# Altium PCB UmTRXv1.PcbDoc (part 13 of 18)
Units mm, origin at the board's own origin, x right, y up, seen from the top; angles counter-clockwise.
Board outline 172 x 113 mm, 6 copper layers (Top Layer, GND, MidLayer1, Mid-Layer 2, InternalPlane2, Bottom Layer); 766 components, 613 nets, 3008 pads, 1360 vias.
Unrouted connection lines stored in the file: 2.
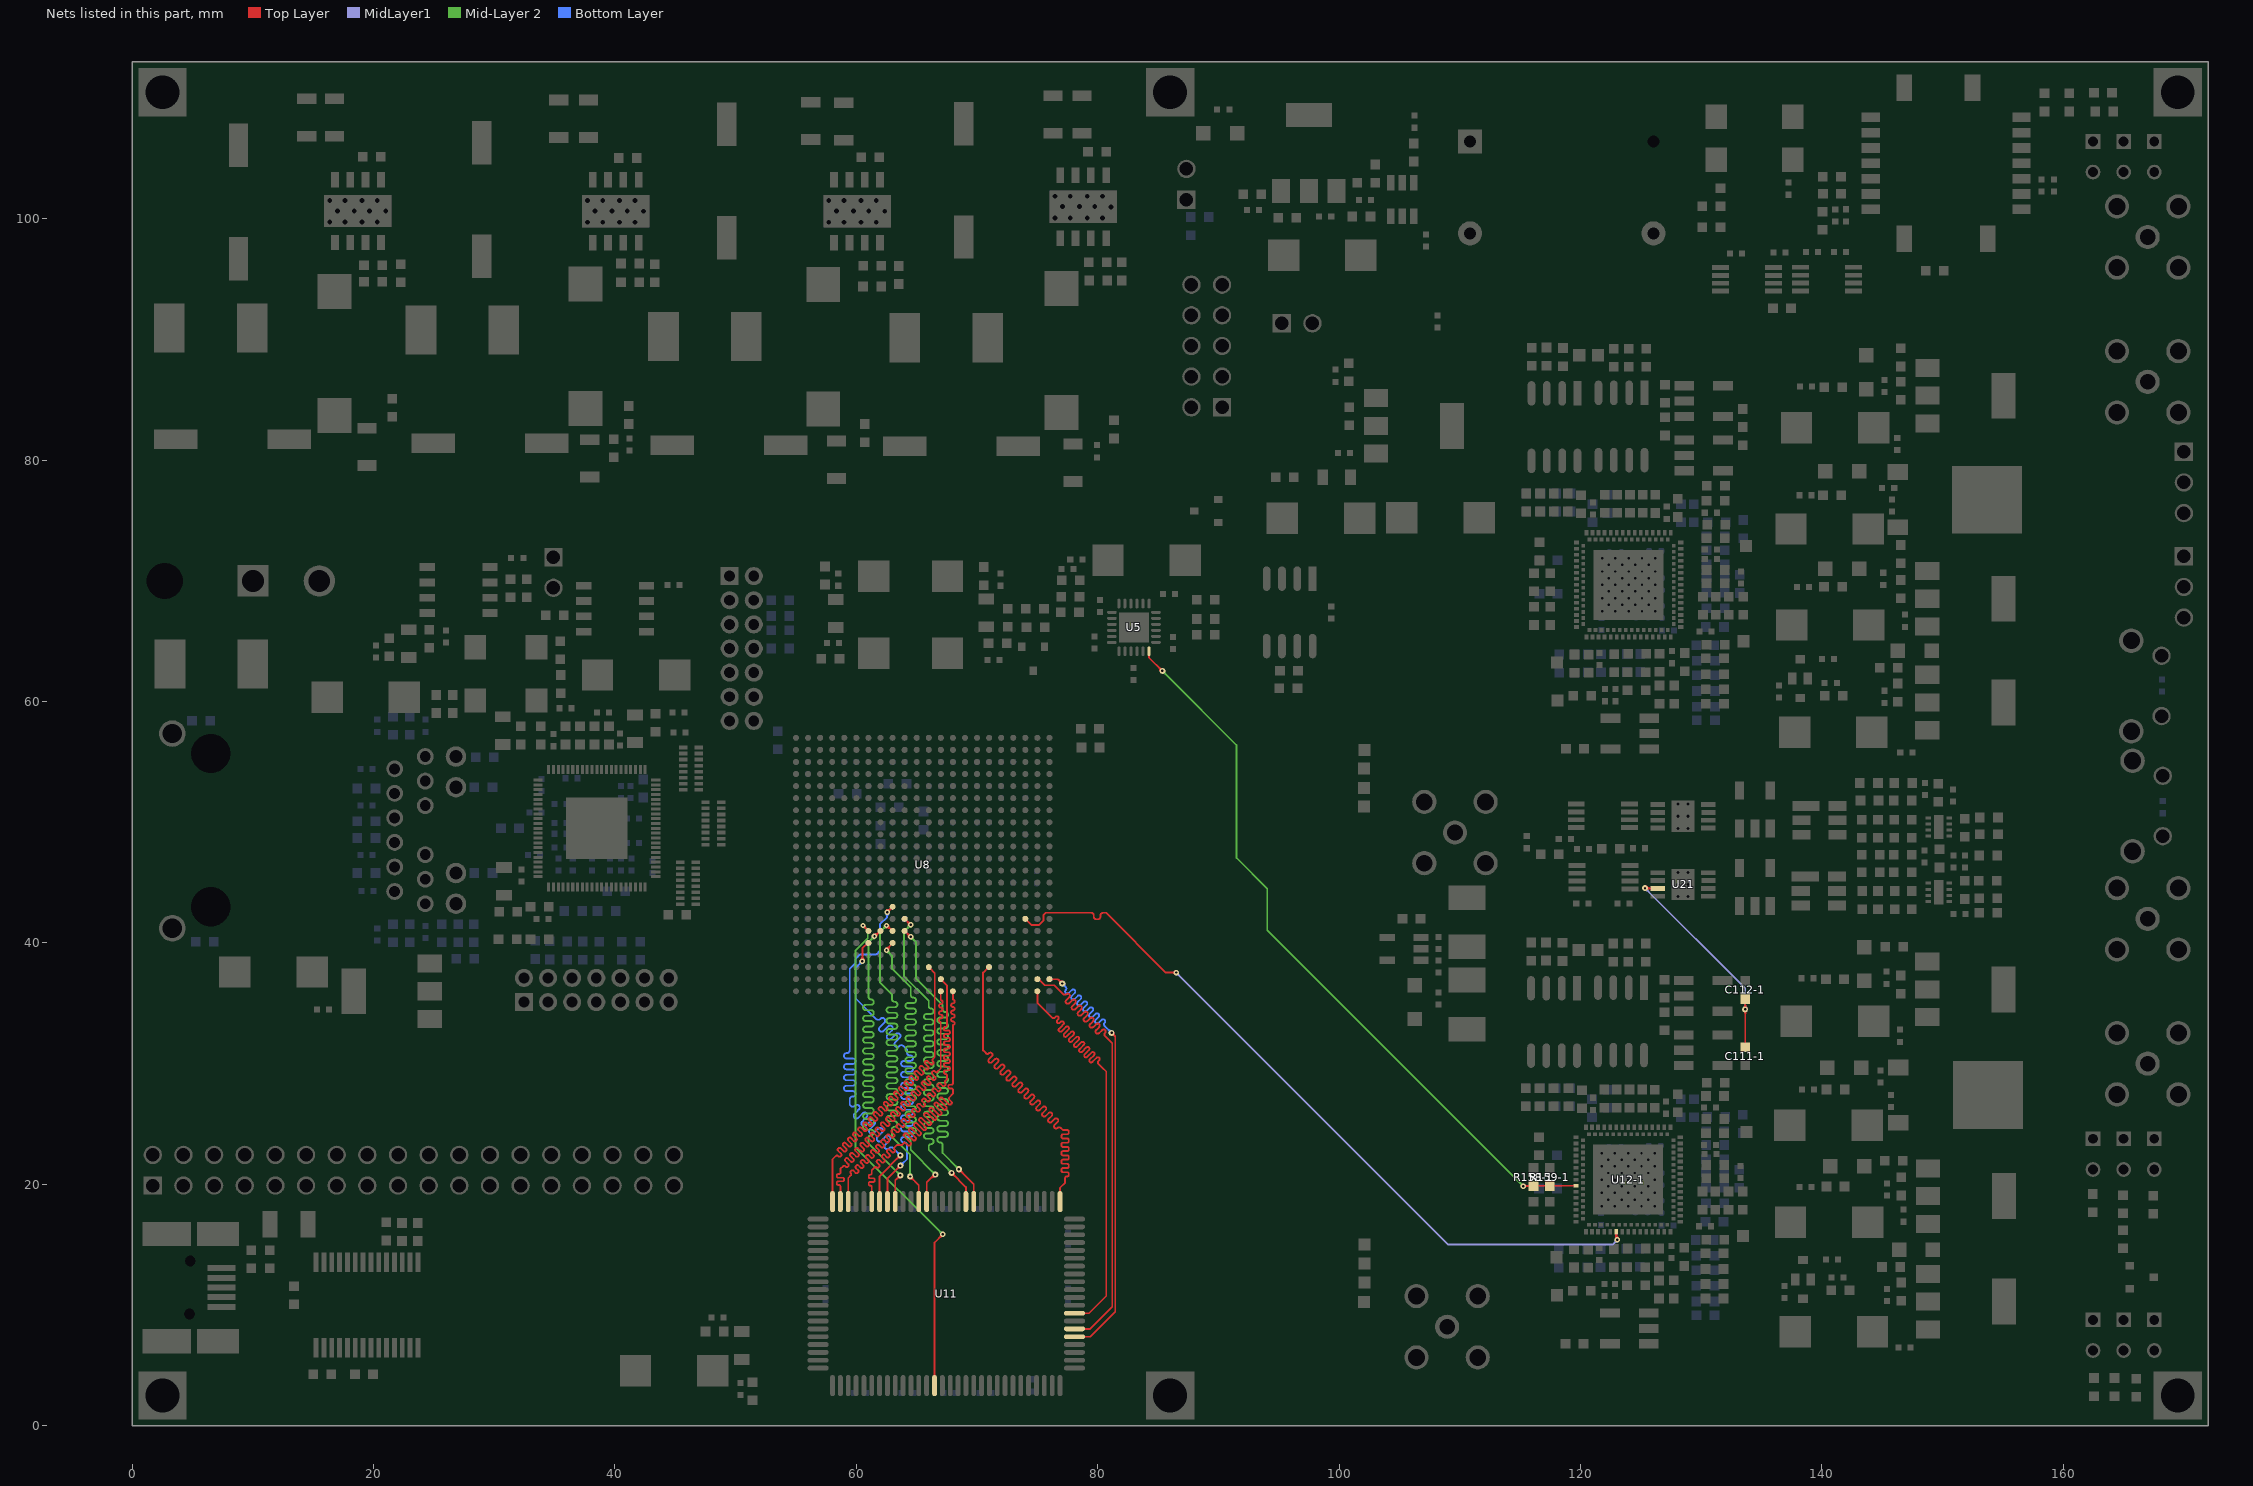
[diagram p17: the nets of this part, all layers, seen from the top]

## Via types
v1: diameter 0.45, hole 0.2, Top Layer to Bottom Layer, tented both sides, 554 vias
v2: diameter 0.5, hole 0.2, Top Layer to Bottom Layer, tented both sides, 468 vias
v3: diameter 0.7, hole 0.3, Top Layer to Bottom Layer, tented both sides, 206 vias
v4: diameter 0.4, hole 0.2, Top Layer to Bottom Layer, tented both sides, 82 vias
v5: diameter 0.8, hole 0.3, Top Layer to Bottom Layer, tented both sides, 16 vias
v6: diameter 0.6, hole 0.25, Top Layer to Bottom Layer, tented both sides, 16 vias
v7: diameter 0.5, hole 0.3, Top Layer to Bottom Layer, tented both sides, 8 vias
v8: diameter 0.7, hole 0.3, Top Layer to Bottom Layer, 4 vias
v9: diameter 0.6, hole 0.3, Top Layer to Bottom Layer, tented both sides, 4 vias
v10: diameter 0.5, hole 0.2, Top Layer to Bottom Layer, 2 vias

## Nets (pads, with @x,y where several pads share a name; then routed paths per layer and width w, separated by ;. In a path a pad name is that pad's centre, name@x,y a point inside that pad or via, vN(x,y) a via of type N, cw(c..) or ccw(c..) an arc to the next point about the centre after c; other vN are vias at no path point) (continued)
RAM_D24: U8.F13 U11.12 | length 44
  Top Layer w0.15: U8.F13@64,41 v1(64.5,40.5) ; v1@64.325,40.5 ccw(c63.903,40.5) 64.201,40.799 ccw(c64.5,41.097) v1@64.5,40.675 ; v2@68.5,21.075 cw(c68.5,20.653) 68.799,20.951 cw(c69.097,21.25) v2@68.675,21.25 ; v2(68.5,21.25) 69.725,20.025 U11.12@69.725,18.575
  Mid-Layer 2 w0.15: v1@64.5,40.325 cw(c64.5,39.903) 64.799,40.201 cw(c65.097,40.5) v1@64.675,40.5 ; v1(64.5,40.5) 64.95,40.05 64.95,37.05 67.15,34.85 67.15,34.5 ccw(c67.375,34.5) 67.375,34.275 cw(c67.375,34.05) 67.6,34.05 cw(c67.375,34.05) 67.375,33.825 66.931,33.825 ccw(c66.931,33.6) 66.706,33.6 ccw(c66.931,33.6) 66.931,33.375 67.369,33.375 cw(c67.369,33.15) 67.594,33.15 cw(c67.369,33.15) 67.369,32.925 66.931,32.925 ccw(c66.931,32.7) 66.706,32.7 ccw(c66.931,32.7) 66.931,32.475 67.369,32.475 cw(c67.369,32.25) 67.594,32.25 cw(c67.369,32.25) 67.369,32.025 66.931,32.025 ccw(c66.931,31.8) 66.706,31.8 ccw(c66.931,31.8) 66.931,31.575 67.369,31.575 cw(c67.369,31.35) 67.594,31.35 cw(c67.369,31.35) 67.369,31.125 66.931,31.125 ccw(c66.931,30.9) 66.706,30.9 ccw(c66.931,30.9) 66.931,30.675 67.369,30.675 cw(c67.369,30.45) 67.594,30.45 cw(c67.369,30.45) 67.369,30.225 66.931,30.225 ccw(c66.931,30) 66.706,30 ccw(c66.931,30) 66.931,29.775 67.369,29.775 cw(c67.369,29.55) 67.594,29.55 cw(c67.369,29.55) 67.369,29.325 66.931,29.325 ccw(c66.931,29.1) 66.706,29.1 ccw(c66.931,29.1) 66.931,28.875 67.369,28.875 cw(c67.369,28.65) 67.594,28.65 cw(c67.369,28.65) 67.369,28.425 66.931,28.425 ccw(c66.931,28.2) 66.706,28.2 ccw(c66.931,28.2) 66.931,27.975 67.369,27.975 cw(c67.369,27.75) 67.594,27.75 cw(c67.369,27.75) 67.369,27.525 66.931,27.525 ccw(c66.931,27.3) 66.706,27.3 ccw(c66.931,27.3) 66.931,27.075 67.369,27.075 cw(c67.369,26.85) 67.594,26.85 cw(c67.369,26.85) 67.369,26.625 66.931,26.625 ccw(c66.931,26.4) 66.706,26.4 ccw(c66.931,26.4) 66.931,26.175 67.369,26.175 cw(c67.369,25.95) 67.594,25.95 cw(c67.369,25.95) 67.369,25.725 66.931,25.725 ccw(c66.931,25.5) 66.706,25.5 ccw(c66.931,25.5) 66.931,25.275 67.369,25.275 cw(c67.369,25.05) 67.594,25.05 cw(c67.369,25.05) 67.369,24.825 66.931,24.825 ccw(c66.931,24.6) 66.706,24.6 ccw(c66.931,24.6) 66.931,24.375 67.369,24.375 cw(c67.369,24.15) 67.594,24.15 cw(c67.369,24.15) 67.369,23.925 66.931,23.925 ccw(c66.931,23.7) 66.706,23.7 ccw(c66.931,23.7) 66.925,23.475 ccw(c66.931,23.7) 66.931,23.475 ; v2@68.325,21.25 ccw(c67.903,21.25) 68.201,21.549 ccw(c68.5,21.847) v2@68.5,21.425 ; v2(68.5,21.25) 67.15,22.6 67.15,23.25 ccw(c66.925,23.25) 66.931,23.475 ; 66.931,23.475 ccw(c66.925,23.25) 66.925,23.475 66.931,23.475
RAM_D25: U8.G13 U11.13 | length 43.7
  Top Layer w0.15: U8.G13@64,42 v1(64.5,41.5) ; v1@64.325,41.5 ccw(c63.903,41.5) 64.201,41.799 ccw(c64.5,42.097) v1@64.5,41.675 ; v2@67.9,20.775 cw(c67.9,20.353) 68.199,20.651 cw(c68.497,20.95) v2@68.075,20.95 ; v2(67.9,20.95) 69.075,19.775 U11.13@69.075,18.575
  Mid-Layer 2 w0.15: v1@64.325,41.5 cw(c63.903,41.5) 64.201,41.201 cw(c64.5,40.903) v1@64.5,41.325 ; v1(64.5,41.5) 63.95,40.95 63.95,37.25 66,35.2 66,34.75 ccw(c66.175,34.75) 66.175,34.575 cw(c66.175,34.35) 66.4,34.35 cw(c66.175,34.35) 66.175,34.125 65.825,34.125 ccw(c65.825,33.9) 65.6,33.9 ccw(c65.825,33.9) 65.825,33.675 66.175,33.675 cw(c66.175,33.45) 66.4,33.45 cw(c66.175,33.45) 66.175,33.225 65.825,33.225 ccw(c65.825,33) 65.6,33 ccw(c65.825,33) 65.825,32.775 66.175,32.775 cw(c66.175,32.55) 66.4,32.55 cw(c66.175,32.55) 66.175,32.325 65.825,32.325 ccw(c65.825,32.1) 65.6,32.1 ccw(c65.825,32.1) 65.825,31.875 66.175,31.875 cw(c66.175,31.65) 66.4,31.65 cw(c66.175,31.65) 66.175,31.425 65.825,31.425 ccw(c65.825,31.2) 65.6,31.2 ccw(c65.825,31.2) 65.825,30.975 66.175,30.975 cw(c66.175,30.75) 66.4,30.75 cw(c66.175,30.75) 66.175,30.525 65.825,30.525 ccw(c65.825,30.3) 65.6,30.3 ccw(c65.825,30.3) 65.825,30.075 66.175,30.075 cw(c66.175,29.85) 66.4,29.85 cw(c66.175,29.85) 66.175,29.625 65.825,29.625 ccw(c65.825,29.4) 65.6,29.4 ccw(c65.825,29.4) 65.825,29.175 66.175,29.175 cw(c66.175,28.95) 66.4,28.95 cw(c66.175,28.95) 66.175,28.725 65.825,28.725 ccw(c65.825,28.5) 65.6,28.5 ccw(c65.825,28.5) 65.825,28.275 66.175,28.275 cw(c66.175,28.05) 66.4,28.05 cw(c66.175,28.05) 66.175,27.825 65.825,27.825 ccw(c65.825,27.6) 65.6,27.6 ccw(c65.825,27.6) 65.825,27.375 66.175,27.375 cw(c66.175,27.15) 66.4,27.15 cw(c66.175,27.15) 66.175,26.925 65.825,26.925 ccw(c65.825,26.7) 65.6,26.7 ccw(c65.825,26.7) 65.825,26.475 66.175,26.475 cw(c66.175,26.25) 66.4,26.25 cw(c66.175,26.25) 66.175,26.025 65.825,26.025 ccw(c65.825,25.8) 65.6,25.8 ccw(c65.825,25.8) 65.825,25.575 66.175,25.575 cw(c66.175,25.35) 66.4,25.35 cw(c66.175,25.35) 66.175,25.125 65.825,25.125 ccw(c65.825,24.9) 65.6,24.9 ccw(c65.825,24.9) 65.825,24.675 66.175,24.675 cw(c66.175,24.45) 66.4,24.45 cw(c66.175,24.45) 66.175,24.225 65.825,24.225 ccw(c65.825,24) 65.6,24 ccw(c65.825,24) 65.825,23.775 66.175,23.775 cw(c66.175,23.55) 66.4,23.55 cw(c66.175,23.55) 66.175,23.325 ccw(c66.175,23.15) 66,23.15 66,22.85 v2(67.9,20.95) ; v2@67.725,20.95 ccw(c67.303,20.95) 67.601,21.249 ccw(c67.9,21.547) v2@67.9,21.125
RAM_D26: U8.C6 U11.1 | length 41.2
  Top Layer w0.15: U8.C6@71,38 70.95,38 70.5,37.55 70.5,31.1 70.75,30.85 ccw(c70.862,30.962) 70.973,30.85 70.985,30.862 cw(c71.109,30.738) 71.233,30.862 cw(c71.109,30.738) 71.233,30.615 71.109,30.491 70.985,30.367 ccw(c71.109,30.243) 70.985,30.12 ccw(c71.109,30.243) 71.233,30.12 71.48,30.367 cw(c71.604,30.243) 71.728,30.367 cw(c71.604,30.243) 71.728,30.12 71.48,29.872 ccw(c71.604,29.748) 71.48,29.625 ccw(c71.604,29.748) 71.728,29.625 71.975,29.872 cw(c72.099,29.748) 72.223,29.872 cw(c72.099,29.748) 72.223,29.625 71.975,29.377 ccw(c72.099,29.254) 71.975,29.13 ccw(c72.099,29.254) 72.223,29.13 72.47,29.377 cw(c72.594,29.254) 72.718,29.377 cw(c72.594,29.254) 72.718,29.13 72.47,28.882 ccw(c72.594,28.759) 72.47,28.635 ccw(c72.594,28.759) 72.718,28.635 72.965,28.882 cw(c73.089,28.759) 73.213,28.882 cw(c73.089,28.759) 73.213,28.635 72.965,28.387 ccw(c73.089,28.264) 72.965,28.14 ccw(c73.089,28.264) 73.213,28.14 73.46,28.387 cw(c73.584,28.264) 73.708,28.387 cw(c73.584,28.264) 73.708,28.14 73.46,27.892 ccw(c73.584,27.769) 73.46,27.645 ccw(c73.584,27.769) 73.708,27.645 73.955,27.892 cw(c74.079,27.769) 74.203,27.892 cw(c74.079,27.769) 74.203,27.645 73.955,27.397 ccw(c74.079,27.274) 73.955,27.15 ccw(c74.079,27.274) 74.203,27.15 74.45,27.397 cw(c74.574,27.274) 74.698,27.397 cw(c74.574,27.274) 74.698,27.15 74.574,27.026 74.45,26.902 ccw(c74.574,26.779) 74.45,26.655 ccw(c74.574,26.779) 74.698,26.655 74.945,26.902 cw(c75.069,26.779) 75.193,26.902 cw(c75.069,26.779) 75.193,26.655 74.945,26.407 ccw(c75.069,26.284) 74.945,26.16 ccw(c75.069,26.284) 75.193,26.16 75.44,26.407 cw(c75.564,26.284) 75.688,26.407 cw(c75.564,26.284) 75.688,26.16 75.44,25.912 ccw(c75.564,25.789) 75.44,25.665 ccw(c75.564,25.789) 75.688,25.665 75.935,25.912 cw(c76.059,25.789) 76.183,25.912 cw(c76.059,25.789) 76.183,25.665 75.935,25.417 ccw(c76.059,25.294) 75.935,25.17 ccw(c76.059,25.294) 76.183,25.17 76.43,25.417 cw(c76.554,25.294) 76.678,25.417 cw(c76.554,25.294) 76.678,25.17 76.43,24.922 ccw(c76.554,24.799) 76.43,24.675 ccw(c76.554,24.799) 76.678,24.675 cw(c76.801,24.551) 76.925,24.675 77.1,24.5 77.477,24.5 cw(c77.477,24.377) 77.6,24.377 77.6,24.272 cw(c77.477,24.272) 77.477,24.15 77.122,24.15 ccw(c77.122,24.027) 77,24.027 77,23.922 ccw(c77.122,23.922) 77.122,23.8 77.477,23.8 cw(c77.477,23.677) 77.6,23.677 77.6,23.572 cw(c77.477,23.572) 77.477,23.45 77.122,23.45 ccw(c77.122,23.327) 77,23.327 77,23.222 ccw(c77.122,23.222) 77.122,23.1 77.477,23.1 cw(c77.477,22.977) 77.6,22.977 77.6,22.872 cw(c77.477,22.872) 77.477,22.75 77.122,22.75 ccw(c77.122,22.627) 77,22.627 77,22.522 ccw(c77.122,22.522) 77.122,22.4 77.477,22.4 cw(c77.477,22.277) 77.6,22.277 77.6,22.172 cw(c77.477,22.172) 77.477,22.05 77.122,22.05 ccw(c77.122,21.927) 77,21.927 77,21.822 ccw(c77.122,21.822) 77.122,21.7 77.477,21.7 cw(c77.477,21.577) 77.6,21.577 77.6,21.472 cw(c77.477,21.472) 77.477,21.35 77.122,21.35 ccw(c77.122,21.227) 77,21.227 77,21.122 ccw(c77.122,21.122) 77.122,21 77.477,21 cw(c77.477,20.877) 77.6,20.877 77.6,20.772 cw(c77.477,20.772) 77.477,20.65 77.422,20.65 ccw(c77.422,20.528) 77.3,20.528 77.3,20.125 76.875,19.7 U11.1@76.875,18.575
RAM_D27: U8.E14 U11.18 | length 44
  Top Layer w0.15: v1(62.5,39.4) 62.5,39.5 U8.E14@63,40 ; v1@62.5,39.575 ccw(c62.5,39.756) 62.628,39.628 ; v1@62.675,39.4 cw(c63.339,39.4) U8.E14@62.869,39.869 ; U11.18@65.825,18.575 65.825,20.175 66.45,20.8 v2(66.55,20.8) ; 66.081,20.431 cw(c66.55,19.961) v2@66.55,20.625 ; 66.322,20.672 ccw(c66.194,20.8) v2@66.375,20.8
  Mid-Layer 2 w0.15: v1@62.5,39.225 cw(c62.5,38.803) 62.799,39.101 cw(c63.097,39.4) v1@62.675,39.4 ; v1(62.5,39.4) 62.95,38.95 62.95,37.896 64.5,36.346 64.5,35.7 ccw(c64.725,35.7) 64.725,35.475 cw(c64.725,35.25) 64.95,35.25 cw(c64.725,35.25) 64.725,35.025 64.287,35.025 ccw(c64.287,34.8) 64.062,34.8 ccw(c64.287,34.8) 64.287,34.575 64.713,34.575 cw(c64.713,34.35) 64.938,34.35 cw(c64.713,34.35) 64.713,34.125 64.287,34.125 ccw(c64.287,33.9) 64.062,33.9 ccw(c64.287,33.9) 64.287,33.675 64.713,33.675 cw(c64.713,33.45) 64.938,33.45 cw(c64.713,33.45) 64.713,33.225 64.287,33.225 ccw(c64.287,33) 64.062,33 ccw(c64.287,33) 64.287,32.775 64.713,32.775 cw(c64.713,32.55) 64.938,32.55 cw(c64.713,32.55) 64.713,32.325 64.287,32.325 ccw(c64.287,32.1) 64.062,32.1 ccw(c64.287,32.1) 64.287,31.875 64.713,31.875 cw(c64.713,31.65) 64.938,31.65 cw(c64.713,31.65) 64.713,31.425 64.287,31.425 ccw(c64.287,31.2) 64.062,31.2 ccw(c64.287,31.2) 64.287,30.975 64.713,30.975 cw(c64.713,30.75) 64.938,30.75 cw(c64.713,30.75) 64.713,30.525 64.287,30.525 ccw(c64.287,30.3) 64.062,30.3 ccw(c64.287,30.3) 64.287,30.075 64.713,30.075 cw(c64.713,29.85) 64.938,29.85 cw(c64.713,29.85) 64.713,29.625 64.287,29.625 ccw(c64.287,29.4) 64.062,29.4 ccw(c64.287,29.4) 64.287,29.175 64.713,29.175 cw(c64.713,28.95) 64.938,28.95 cw(c64.713,28.95) 64.713,28.725 64.287,28.725 ccw(c64.287,28.5) 64.062,28.5 ccw(c64.287,28.5) 64.287,28.275 64.713,28.275 cw(c64.713,28.05) 64.938,28.05 cw(c64.713,28.05) 64.713,27.825 64.286,27.825 ccw(c64.286,27.6) 64.062,27.6 ccw(c64.286,27.6) 64.286,27.375 64.713,27.375 cw(c64.713,27.15) 64.938,27.15 cw(c64.713,27.15) 64.713,26.925 64.286,26.925 ccw(c64.286,26.7) 64.062,26.7 ccw(c64.286,26.7) 64.286,26.475 64.713,26.475 cw(c64.713,26.25) 64.938,26.25 cw(c64.713,26.25) 64.713,26.025 64.286,26.025 ccw(c64.286,25.8) 64.062,25.8 ccw(c64.286,25.8) 64.286,25.575 64.713,25.575 cw(c64.713,25.35) 64.938,25.35 cw(c64.713,25.35) 64.713,25.125 64.286,25.125 ccw(c64.286,24.9) 64.062,24.9 ccw(c64.286,24.9) 64.286,24.675 64.713,24.675 cw(c64.713,24.45) 64.938,24.45 cw(c64.713,24.45) 64.713,24.225 64.286,24.225 ccw(c64.286,24) 64.062,24 ccw(c64.286,24) 64.286,23.775 64.325,23.775 cw(c64.325,23.6) 64.5,23.6 64.5,22.85 v2(66.55,20.8) ; v2@66.375,20.8 ccw(c65.953,20.8) 66.251,21.099 ccw(c66.55,21.397) v2@66.55,20.975
RAM_D28: U8.F14 U11.19 | length 43.9
  Top Layer w0.15: v1@62.5,41.275 cw(c62.5,40.732) U8.F14@62.884,41.116 ; v1(62.5,41.45) 62.55,41.45 U8.F14@63,41 ; v1@62.675,41.45 ccw(c62.977,41.45) 62.763,41.237 ; v2@64.45,20.475 cw(c64.45,20.053) 64.749,20.351 cw(c65.047,20.65) v2@64.625,20.65 ; v2(64.45,20.65) 65.175,19.925 U11.19@65.175,18.575
  Mid-Layer 2 w0.15: v1@62.325,41.45 cw(c61.903,41.45) 62.201,41.151 cw(c62.5,40.853) v1@62.5,41.275 ; v1@62.6,41.45 v1(62.5,41.45) 61.95,40.9 61.95,36.75 62.95,35.75 62.95,35.35 ccw(c63.175,35.35) 63.175,35.125 cw(c63.175,34.9) 63.4,34.9 cw(c63.175,34.9) 63.175,34.675 62.725,34.675 ccw(c62.725,34.45) 62.5,34.45 ccw(c62.725,34.45) 62.725,34.225 63.175,34.225 cw(c63.175,34) 63.4,34 cw(c63.175,34) 63.175,33.775 62.725,33.775 ccw(c62.725,33.55) 62.5,33.55 ccw(c62.725,33.55) 62.725,33.325 63.175,33.325 cw(c63.175,33.1) 63.4,33.1 cw(c63.175,33.1) 63.175,32.875 62.725,32.875 ccw(c62.725,32.65) 62.5,32.65 ccw(c62.725,32.65) 62.725,32.425 63.175,32.425 cw(c63.175,32.2) 63.4,32.2 cw(c63.175,32.2) 63.175,31.975 62.725,31.975 ccw(c62.725,31.75) 62.5,31.75 ccw(c62.725,31.75) 62.725,31.525 63.175,31.525 cw(c63.175,31.3) 63.4,31.3 cw(c63.175,31.3) 63.175,31.075 62.725,31.075 ccw(c62.725,30.85) 62.5,30.85 ccw(c62.725,30.85) 62.725,30.625 63.175,30.625 cw(c63.175,30.4) 63.4,30.4 cw(c63.175,30.4) 63.175,30.175 62.725,30.175 ccw(c62.725,29.95) 62.5,29.95 ccw(c62.725,29.95) 62.725,29.725 63.175,29.725 cw(c63.175,29.5) 63.4,29.5 cw(c63.175,29.5) 63.175,29.275 62.725,29.275 ccw(c62.725,29.05) 62.5,29.05 ccw(c62.725,29.05) 62.725,28.825 63.175,28.825 cw(c63.175,28.6) 63.4,28.6 cw(c63.175,28.6) 63.175,28.375 62.725,28.375 ccw(c62.725,28.15) 62.5,28.15 ccw(c62.725,28.15) 62.725,27.925 63.175,27.925 cw(c63.175,27.7) 63.4,27.7 cw(c63.175,27.7) 63.175,27.475 62.725,27.475 ccw(c62.725,27.25) 62.5,27.25 ccw(c62.725,27.25) 62.725,27.025 63.175,27.025 cw(c63.175,26.8) 63.4,26.8 cw(c63.175,26.8) 63.175,26.575 62.725,26.575 ccw(c62.725,26.35) 62.5,26.35 ccw(c62.725,26.35) 62.725,26.125 63.175,26.125 cw(c63.175,25.9) 63.4,25.9 cw(c63.175,25.9) 63.175,25.675 62.725,25.675 ccw(c62.725,25.45) 62.5,25.45 ccw(c62.725,25.45) 62.725,25.225 63.175,25.225 cw(c63.175,25) 63.4,25 cw(c63.175,25) 63.175,24.775 ccw(c63.175,24.55) 62.95,24.55 62.95,23.95 64.45,22.45 v2(64.45,20.65) ; v2@64.326,20.774 ccw(c64.028,21.072) 64.45,21.072 ccw(c64.872,21.072) v2@64.574,20.774
RAM_D29: U8.F15 U11.22 | length 44
  Top Layer w0.15: v1(61.5,40.55) 61.55,40.55 U8.F15@62,41 ; v1@61.5,40.725 ccw(c61.5,41.268) U8.F15@61.884,40.884 ; v1@61.675,40.55 cw(c61.977,40.55) 61.763,40.763 ; U11.22@63.225,18.575 63.225,20.325 v2(63.65,20.75) ; v2@63.475,20.75 cw(c63.053,20.75) 63.351,20.451 cw(c63.65,20.153) v2@63.65,20.575
  Mid-Layer 2 w0.15: v1@61.325,40.55 cw(c60.903,40.55) 61.201,40.251 cw(c61.5,39.953) v1@61.5,40.375 ; v1(61.5,40.55) 61,40.05 61,35.55 ccw(c61.225,35.55) 61.219,35.325 ; v2@63.475,20.75 ccw(c63.053,20.75) 63.351,21.049 ccw(c63.65,21.347) v2@63.65,20.925 ; v2(63.65,20.75) 61,23.4 61,23.85 cw(c61.225,23.85) 61.225,24.075 ccw(c61.225,24.3) 61.45,24.3 ccw(c61.225,24.3) 61.225,24.525 60.782,24.525 cw(c60.782,24.75) 60.557,24.75 cw(c60.782,24.75) 60.782,24.975 61.218,24.975 ccw(c61.218,25.2) 61.443,25.2 ccw(c61.218,25.2) 61.218,25.425 60.782,25.425 cw(c60.782,25.65) 60.557,25.65 cw(c60.782,25.65) 60.782,25.875 61.218,25.875 ccw(c61.218,26.1) 61.443,26.1 ccw(c61.218,26.1) 61.218,26.325 60.782,26.325 cw(c60.782,26.55) 60.557,26.55 cw(c60.782,26.55) 60.782,26.775 61.218,26.775 ccw(c61.218,27) 61.443,27 ccw(c61.218,27) 61.218,27.225 60.782,27.225 cw(c60.782,27.45) 60.557,27.45 cw(c60.782,27.45) 60.782,27.675 61.218,27.675 ccw(c61.218,27.9) 61.443,27.9 ccw(c61.218,27.9) 61.218,28.125 60.782,28.125 cw(c60.782,28.35) 60.557,28.35 cw(c60.782,28.35) 60.782,28.575 61.218,28.575 ccw(c61.218,28.8) 61.443,28.8 ccw(c61.218,28.8) 61.218,29.025 60.782,29.025 cw(c60.782,29.25) 60.557,29.25 cw(c60.782,29.25) 60.782,29.475 61.218,29.475 ccw(c61.218,29.7) 61.443,29.7 ccw(c61.218,29.7) 61.218,29.925 60.782,29.925 cw(c60.782,30.15) 60.557,30.15 cw(c60.782,30.15) 60.782,30.375 61.218,30.375 ccw(c61.218,30.6) 61.443,30.6 ccw(c61.218,30.6) 61.218,30.825 60.782,30.825 cw(c60.782,31.05) 60.557,31.05 cw(c60.782,31.05) 60.782,31.275 61.218,31.275 ccw(c61.218,31.5) 61.443,31.5 ccw(c61.218,31.5) 61.218,31.725 60.782,31.725 cw(c60.782,31.95) 60.557,31.95 cw(c60.782,31.95) 60.782,32.175 61.218,32.175 ccw(c61.218,32.4) 61.443,32.4 ccw(c61.218,32.4) 61.218,32.625 60.782,32.625 cw(c60.782,32.85) 60.557,32.85 cw(c60.782,32.85) 60.782,33.075 61.218,33.075 ccw(c61.218,33.3) 61.443,33.3 ccw(c61.218,33.3) 61.218,33.525 60.782,33.525 cw(c60.782,33.75) 60.557,33.75 cw(c60.782,33.75) 60.782,33.975 61.218,33.975 ccw(c61.218,34.2) 61.443,34.2 ccw(c61.218,34.2) 61.218,34.425 60.782,34.425 cw(c60.782,34.65) 60.557,34.65 cw(c60.782,34.65) 60.782,34.875 61.218,34.875 ccw(c61.218,35.1) 61.443,35.1 ccw(c61.218,35.1) 61.224,35.325 ; 61.219,35.325 ccw(c61.225,35.55) 61.224,35.325 ; 61.219,35.325 cw(c61.218,35.1) 61.224,35.325 ; 61.219,35.325 61.224,35.325
RAM_D30: U8.E16 U11.23 | length 44
  Top Layer w0.15: v1@60.376,38.624 ccw(c60.078,38.922) 60.5,38.922 ccw(c60.922,38.922) v1@60.624,38.624 ; v1(60.5,38.5) 60.5,39.55 U8.E16@60.975,40.025 ; U11.23@62.575,18.575 62.575,20.475 v2(63.65,21.55) ; v2@63.475,21.55 cw(c63.053,21.55) 63.351,21.251 cw(c63.65,20.953) v2@63.65,21.375
  Bottom Layer w0.15: v1@60.325,38.5 cw(c59.903,38.5) 60.201,38.201 cw(c60.5,37.903) v1@60.5,38.325 ; v1(60.5,38.5) 59.95,37.95 59.95,35.4 61.654,33.696 ccw(c61.814,33.855) 61.973,33.696 62.002,33.725 cw(c62.161,33.566) 62.32,33.725 cw(c62.161,33.566) 62.32,33.407 62.132,33.218 61.943,33.03 ccw(c62.102,32.871) 61.943,32.712 ccw(c62.102,32.871) 62.261,32.712 62.45,32.9 62.638,33.089 cw(c62.797,32.929) 62.957,33.089 cw(c62.797,32.929) 62.957,32.77 62.768,32.582 62.58,32.393 ccw(c62.739,32.234) 62.58,32.075 ccw(c62.739,32.234) 62.898,32.075 63.086,32.264 63.275,32.452 cw(c63.434,32.293) 63.593,32.452 cw(c63.434,32.293) 63.593,32.134 63.405,31.945 63.216,31.757 ccw(c63.375,31.598) 63.216,31.439 ccw(c63.375,31.598) 63.534,31.439 63.564,31.468 cw(c63.723,31.309) 63.882,31.468 64.2,31.15 64.2,30.9 ccw(c64.425,30.9) 64.425,30.675 64.467,30.675 cw(c64.467,30.45) 64.692,30.45 cw(c64.467,30.45) 64.467,30.225 63.933,30.225 ccw(c63.933,30) 63.708,30 ccw(c63.933,30) 63.933,29.775 64.467,29.775 cw(c64.467,29.55) 64.692,29.55 cw(c64.467,29.55) 64.467,29.325 63.933,29.325 ccw(c63.933,29.1) 63.708,29.1 ccw(c63.933,29.1) 63.933,28.875 64.467,28.875 cw(c64.467,28.65) 64.692,28.65 cw(c64.467,28.65) 64.467,28.425 63.933,28.425 ccw(c63.933,28.2) 63.708,28.2 ccw(c63.933,28.2) 63.933,27.975 64.467,27.975 cw(c64.467,27.75) 64.692,27.75 cw(c64.467,27.75) 64.467,27.525 63.933,27.525 ccw(c63.933,27.3) 63.708,27.3 ccw(c63.933,27.3) 63.933,27.075 64.467,27.075 cw(c64.467,26.85) 64.692,26.85 cw(c64.467,26.85) 64.467,26.625 63.933,26.625 ccw(c63.933,26.4) 63.708,26.4 ccw(c63.933,26.4) 63.933,26.175 64.467,26.175 cw(c64.467,25.95) 64.692,25.95 cw(c64.467,25.95) 64.467,25.725 63.933,25.725 ccw(c63.933,25.5) 63.708,25.5 ccw(c63.933,25.5) 63.933,25.275 64.467,25.275 cw(c64.467,25.05) 64.692,25.05 cw(c64.467,25.05) 64.467,24.825 63.933,24.825 ccw(c63.933,24.6) 63.708,24.6 ccw(c63.933,24.6) 63.933,24.375 64.467,24.375 cw(c64.467,24.15) 64.692,24.15 cw(c64.467,24.15) 64.467,23.925 63.933,23.925 ccw(c63.933,23.7) 63.708,23.7 ccw(c63.933,23.7) 63.933,23.475 63.975,23.475 cw(c63.975,23.25) 64.2,23.25 64.2,22.1 v2(63.65,21.55) ; v2@63.65,21.725 ccw(c63.65,22.147) 63.949,21.849 ccw(c64.247,21.55) v2@63.825,21.55
RAM_D31: U8.H14 U11.24 | length 45.4
  Top Layer w0.15: U11.24@61.925,18.575 61.925,20.675 v2(63.65,22.4) ; v1@62.55,42.65 v1(62.55,42.55) U8.H14@63,43 ; v1@62.55,42.725 ccw(c62.55,43.147) 62.849,42.849 ccw(c63.147,42.55) v1@62.725,42.55 ; v2@63.475,22.4 cw(c63.053,22.4) 63.351,22.101 cw(c63.65,21.803) v2@63.65,22.225
  Bottom Layer w0.15: 61.675,39.075 61.65,39.05 60.325,39.05 59.925,38.65 59.925,38.324 59.45,37.849 59.45,31.1 cw(c59.225,31.1) 59.225,30.875 59.191,30.875 ccw(c59.191,30.65) 58.966,30.65 ccw(c59.191,30.65) 59.191,30.425 59.709,30.425 cw(c59.709,30.2) 59.934,30.2 cw(c59.709,30.2) 59.709,29.975 59.191,29.975 ccw(c59.191,29.75) 58.966,29.75 ccw(c59.191,29.75) 59.191,29.525 59.709,29.525 cw(c59.709,29.3) 59.934,29.3 cw(c59.709,29.3) 59.709,29.075 59.191,29.075 ccw(c59.191,28.85) 58.966,28.85 ccw(c59.191,28.85) 59.191,28.625 59.709,28.625 cw(c59.709,28.4) 59.934,28.4 cw(c59.709,28.4) 59.709,28.175 59.191,28.175 ccw(c59.191,27.95) 58.966,27.95 ccw(c59.191,27.95) 59.191,27.725 59.709,27.725 cw(c59.709,27.5) 59.934,27.5 cw(c59.709,27.5) 59.709,27.275 59.675,27.275 ccw(c59.675,27.05) 59.45,27.05 59.45,26.6 59.55,26.5 ccw(c59.709,26.659) 59.868,26.5 59.892,26.524 cw(c60.051,26.365) 60.21,26.524 cw(c60.051,26.365) 60.21,26.206 60.027,26.023 59.844,25.84 ccw(c60.003,25.681) 59.844,25.522 ccw(c60.003,25.681) 60.162,25.522 60.345,25.705 60.528,25.888 cw(c60.687,25.729) 60.847,25.888 cw(c60.687,25.729) 60.847,25.57 60.664,25.386 60.48,25.203 ccw(c60.64,25.044) 60.48,24.885 ccw(c60.64,25.044) 60.799,24.885 60.982,25.068 61.165,25.251 cw(c61.324,25.092) 61.483,25.251 cw(c61.324,25.092) 61.483,24.933 61.3,24.75 61.117,24.567 ccw(c61.276,24.408) 61.117,24.249 ccw(c61.276,24.408) 61.435,24.249 61.618,24.432 61.801,24.615 cw(c61.96,24.456) 62.119,24.615 cw(c61.96,24.456) 62.119,24.297 61.936,24.114 61.753,23.931 ccw(c61.912,23.772) 61.753,23.612 ccw(c61.912,23.772) 62.071,23.612 62.255,23.795 62.438,23.979 cw(c62.597,23.819) 62.756,23.979 cw(c62.597,23.819) 62.756,23.66 62.573,23.477 62.39,23.294 ccw(c62.549,23.135) 62.39,22.976 ccw(c62.549,23.135) 62.708,22.976 62.732,23 cw(c62.891,22.841) 63.05,23 v2(63.65,22.4) ; 61.676,39.075 61.95,39.349 61.95,41.546 62.55,42.146 ; v1@62.43,42.422 cw(c62.172,42.146) 62.55,42.146 ; v1(62.55,42.55) 62.55,42.146 ; v1@62.67,42.422 ccw(c62.928,42.146) 62.55,42.146 ; v2@63.475,22.4 ccw(c63.053,22.4) 63.351,22.699 ccw(c63.65,22.997) v2@63.65,22.575
RAM_D32: U8.A9 U11.25 | length 41.1
  Top Layer w0.15: U11.25@61.275,18.575 61.275,19.78 ccw(c61.155,19.78) 61.155,19.9 61.145,19.9 cw(c61.145,20.02) 61.025,20.02 61.025,20.08 cw(c61.145,20.08) 61.145,20.2 61.405,20.2 ccw(c61.405,20.32) 61.525,20.32 61.525,20.38 ccw(c61.405,20.38) 61.405,20.5 61.145,20.5 cw(c61.145,20.62) 61.025,20.62 61.025,20.68 cw(c61.145,20.68) 61.145,20.8 61.155,20.8 ccw(c61.155,20.92) 61.275,20.92 61.275,21.175 61.508,21.408 cw(c61.593,21.323) 61.678,21.408 61.685,21.401 ccw(c61.77,21.486) 61.855,21.401 ; 61.713,21.797 61.897,21.613 cw(c61.812,21.529) 61.897,21.444 61.855,21.401 ; 61.713,21.797 cw(c61.798,21.882) 61.713,21.967 61.756,22.009 ; 61.756,22.01 cw(c61.841,21.925) 61.926,22.009 62.109,21.826 ccw(c62.194,21.91) 62.279,21.825 62.322,21.868 ccw(c62.237,21.953) 62.322,22.038 62.138,22.222 cw(c62.223,22.306) 62.138,22.391 62.18,22.434 cw(c62.265,22.349) 62.35,22.434 62.534,22.25 ccw(c62.619,22.335) 62.703,22.25 62.746,22.292 ccw(c62.661,22.377) 62.746,22.462 62.654,22.554 62.562,22.646 cw(c62.647,22.731) 62.562,22.815 62.604,22.858 cw(c62.689,22.773) 62.774,22.858 62.958,22.674 ccw(c63.043,22.759) 63.128,22.674 63.17,22.716 ccw(c63.085,22.801) 63.17,22.886 63.163,22.893 ; 63.163,22.893 cw(c63.248,22.978) 63.163,23.063 63.35,23.25 63.75,23.25 63.921,23.421 cw(c64.006,23.336) 64.091,23.421 64.275,23.237 ccw(c64.36,23.322) 64.444,23.237 64.487,23.28 ccw(c64.402,23.365) 64.487,23.449 64.218,23.718 63.949,23.987 cw(c64.034,24.072) 63.949,24.156 63.992,24.199 cw(c64.077,24.114) 64.161,24.199 64.699,23.662 ccw(c64.784,23.746) 64.869,23.662 64.911,23.704 ccw(c64.826,23.789) 64.911,23.874 64.642,24.142 64.374,24.411 cw(c64.459,24.496) 64.374,24.581 64.416,24.623 cw(c64.501,24.538) 64.586,24.623 65.123,24.086 ccw(c65.208,24.171) 65.293,24.086 65.335,24.128 ccw(c65.251,24.213) 65.336,24.298 ; 65.335,24.298 64.798,24.835 cw(c64.883,24.92) 64.798,25.005 64.84,25.048 cw(c64.925,24.963) 65.01,25.048 65.279,24.779 65.548,24.51 ; 65.548,24.51 ccw(c65.632,24.595) 65.717,24.51 65.76,24.553 ; 65.76,24.553 ccw(c65.675,24.637) 65.76,24.722 65.222,25.26 cw(c65.307,25.345) 65.222,25.429 65.265,25.472 cw(c65.35,25.387) 65.434,25.472 65.972,24.934 ccw(c66.057,25.019) 66.141,24.934 ; 66.142,24.934 66.184,24.977 ccw(c66.099,25.062) 66.184,25.146 ; 66.184,25.147 65.915,25.415 65.647,25.684 cw(c65.731,25.769) 65.646,25.854 65.689,25.896 cw(c65.774,25.811) 65.859,25.896 66.396,25.359 ; 66.396,25.359 ccw(c66.481,25.444) 66.566,25.359 66.608,25.401 ccw(c66.523,25.486) 66.608,25.571 66.34,25.84 66.071,26.108 cw(c66.156,26.193) 66.071,26.278 66.113,26.32 cw(c66.198,26.235) 66.283,26.32 66.82,25.783 ccw(c66.905,25.868) 66.99,25.783 67.032,25.825 ccw(c66.948,25.91) 67.033,25.995 66.495,26.532 cw(c66.58,26.617) 66.495,26.702 ; 66.495,26.702 66.537,26.745 cw(c66.622,26.66) 66.707,26.745 66.976,26.476 67.245,26.207 ccw(c67.329,26.292) 67.414,26.207 67.457,26.25 ccw(c67.372,26.334) 67.457,26.419 66.919,26.957 cw(c67.004,27.042) 66.919,27.126 66.962,27.169 cw(c67.047,27.084) 67.131,27.169 67.669,26.631 ccw(c67.754,26.716) 67.838,26.631 67.881,26.674 ccw(c67.796,26.759) 67.881,26.844 67.697,27.027 cw(c67.782,27.112) 67.697,27.197 68,27.5 68,27.83 ccw(c67.88,27.83) 67.88,27.95 67.738,27.95 cw(c67.738,28.07) 67.618,28.07 67.618,28.13 cw(c67.738,28.13) 67.738,28.25 67.88,28.25 ccw(c67.88,28.37) 68,28.37 68,33.2 ccw(c68,33.35) 68,33.5 cw(c68,33.65) 68,33.8 ccw(c68,33.95) 68,34.1 cw(c68,34.25) 68,34.4 ccw(c68,34.55) 68,34.7 cw(c68,34.85) 68,35 ccw(c68,35.15) 68,35.3 U8.A9@68,36
RAM_D33: U8.B10 U11.28 | length 41.3
  Top Layer w0.15: U11.28@59.325,18.575 59.325,20.525 59.546,20.746 ccw(c59.461,20.831) 59.546,20.916 59.539,20.923 cw(c59.624,21.008) 59.539,21.093 59.582,21.135 cw(c59.666,21.05) 59.751,21.135 59.843,21.043 59.935,20.951 ccw(c60.02,21.036) 60.105,20.951 60.147,20.994 ccw(c60.062,21.079) 60.147,21.163 59.963,21.347 cw(c60.048,21.432) 59.963,21.517 60.006,21.559 cw(c60.091,21.475) 60.176,21.559 60.359,21.376 ccw(c60.444,21.46) 60.529,21.375 60.572,21.418 ccw(c60.487,21.503) 60.572,21.588 60.388,21.772 cw(c60.473,21.856) 60.388,21.941 60.43,21.984 cw(c60.515,21.899) 60.6,21.984 60.784,21.8 ccw(c60.868,21.885) 60.953,21.8 60.996,21.842 ccw(c60.911,21.927) 60.996,22.012 60.904,22.104 60.812,22.196 ; 60.812,22.196 cw(c60.897,22.281) 60.812,22.365 60.854,22.408 cw(c60.939,22.323) 61.024,22.408 61.208,22.224 ccw(c61.293,22.309) 61.378,22.224 61.42,22.266 ccw(c61.335,22.351) 61.42,22.436 61.236,22.62 cw(c61.321,22.705) 61.236,22.79 ; 61.236,22.79 61.279,22.832 cw(c61.363,22.747) 61.448,22.832 ; 61.448,22.832 61.54,22.74 61.632,22.648 ; 61.632,22.648 ccw(c61.717,22.733) 61.802,22.648 ; 61.802,22.648 61.844,22.691 ccw(c61.759,22.776) 61.844,22.86 ; 61.844,22.86 61.66,23.044 cw(c61.745,23.129) 61.66,23.214 61.703,23.256 cw(c61.788,23.172) 61.872,23.257 61.965,23.165 62.056,23.073 ; 62.057,23.072 ccw(c62.141,23.157) 62.226,23.073 62.269,23.115 ; 62.269,23.115 ccw(c62.184,23.2) 62.269,23.285 62.085,23.469 cw(c62.17,23.553) 62.085,23.638 62.127,23.681 cw(c62.212,23.596) 62.297,23.681 ; 62.297,23.681 62.481,23.497 ccw(c62.566,23.582) 62.65,23.497 62.693,23.539 ccw(c62.608,23.624) 62.693,23.709 62.601,23.801 62.509,23.893 ; 62.509,23.893 cw(c62.594,23.978) 62.509,24.063 62.551,24.105 cw(c62.636,24.02) 62.721,24.105 62.905,23.921 ccw(c62.99,24.006) 63.075,23.921 63.117,23.964 ccw(c63.032,24.048) 63.117,24.133 62.933,24.317 cw(c63.018,24.402) 62.933,24.487 62.976,24.529 cw(c63.061,24.444) 63.145,24.529 63.329,24.345 ccw(c63.414,24.43) 63.499,24.345 63.541,24.388 ccw(c63.457,24.473) 63.542,24.557 63.358,24.741 cw(c63.442,24.826) 63.358,24.911 63.4,24.953 cw(c63.485,24.869) 63.569,24.954 63.662,24.862 63.753,24.77 ccw(c63.838,24.854) 63.923,24.77 63.966,24.812 ccw(c63.881,24.897) 63.966,24.982 63.782,25.166 cw(c63.867,25.25) 63.782,25.335 63.824,25.378 cw(c63.909,25.293) 63.994,25.378 64.178,25.194 ccw(c64.263,25.279) 64.347,25.194 64.39,25.236 ccw(c64.305,25.321) 64.39,25.406 64.298,25.498 64.206,25.59 cw(c64.291,25.675) 64.206,25.759 64.248,25.802 cw(c64.333,25.717) 64.418,25.802 64.602,25.618 ccw(c64.687,25.703) 64.772,25.618 64.814,25.661 ; 64.814,25.661 ccw(c64.729,25.745) 64.814,25.83 64.722,25.922 64.63,26.014 cw(c64.715,26.099) 64.63,26.184 64.673,26.226 cw(c64.758,26.141) 64.842,26.226 65.026,26.042 ccw(c65.111,26.127) 65.196,26.042 ; 65.196,26.042 65.238,26.085 ccw(c65.154,26.17) 65.239,26.254 65.055,26.438 cw(c65.139,26.523) 65.054,26.608 65.097,26.651 cw(c65.182,26.566) 65.267,26.651 65.359,26.559 65.451,26.467 ccw(c65.535,26.552) 65.62,26.467 65.663,26.509 ccw(c65.578,26.594) 65.663,26.679 65.479,26.863 cw(c65.564,26.948) 65.479,27.032 65.521,27.075 cw(c65.606,26.99) 65.691,27.075 65.875,26.891 ccw(c65.96,26.976) 66.044,26.891 66.087,26.933 ccw(c66.002,27.018) 66.087,27.103 65.995,27.195 65.903,27.287 cw(c65.988,27.372) 65.903,27.456 65.946,27.499 cw(c66.03,27.414) 66.115,27.499 66.299,27.315 ccw(c66.384,27.4) 66.469,27.315 66.511,27.358 ccw(c66.426,27.442) 66.511,27.527 66.419,27.619 66.327,27.711 cw(c66.412,27.796) 66.327,27.881 66.37,27.923 cw(c66.455,27.838) 66.539,27.923 66.723,27.739 ccw(c66.808,27.824) 66.893,27.739 66.935,27.782 ccw(c66.851,27.867) 66.936,27.951 66.752,28.135 cw(c66.836,28.22) 66.751,28.305 66.794,28.348 cw(c66.879,28.263) 66.964,28.348 67.056,28.256 67.148,28.164 ccw(c67.232,28.249) 67.317,28.164 67.36,28.206 ccw(c67.275,28.291) 67.36,28.376 67.353,28.383 cw(c67.438,28.468) 67.353,28.553 67.5,28.7 67.5,29.03 ccw(c67.38,29.03) 67.38,29.15 67.37,29.15 cw(c67.37,29.27) 67.25,29.27 67.25,29.33 cw(c67.37,29.33) 67.37,29.45 67.63,29.45 ccw(c67.63,29.57) 67.75,29.57 67.75,29.63 ccw(c67.63,29.63) 67.63,29.75 67.37,29.75 cw(c67.37,29.87) 67.25,29.87 67.25,29.93 cw(c67.37,29.93) 67.37,30.05 67.63,30.05 ccw(c67.63,30.17) 67.75,30.17 67.75,30.23 ccw(c67.63,30.23) 67.63,30.35 67.37,30.35 cw(c67.37,30.47) 67.25,30.47 67.25,30.53 cw(c67.37,30.53) 67.37,30.65 67.63,30.65 ccw(c67.63,30.77) 67.75,30.77 67.75,30.83 ccw(c67.63,30.83) 67.63,30.95 67.37,30.95 cw(c67.37,31.07) 67.25,31.07 67.25,31.13 cw(c67.37,31.13) 67.37,31.25 67.63,31.25 ccw(c67.63,31.37) 67.75,31.37 67.75,31.43 ccw(c67.63,31.43) 67.63,31.55 67.37,31.55 cw(c67.37,31.67) 67.25,31.67 67.25,31.73 cw(c67.37,31.73) 67.37,31.85 67.63,31.85 ccw(c67.63,31.97) 67.75,31.97 67.75,32.03 ccw(c67.63,32.03) 67.63,32.15 67.37,32.15 cw(c67.37,32.27) 67.25,32.27 67.25,32.33 cw(c67.37,32.33) 67.37,32.45 67.63,32.45 ccw(c67.63,32.57) 67.75,32.57 67.75,32.63 ccw(c67.63,32.63) 67.63,32.75 67.37,32.75 cw(c67.37,32.87) 67.25,32.87 67.25,32.93 cw(c67.37,32.93) 67.37,33.05 67.38,33.05 ccw(c67.38,33.17) 67.5,33.17 67.5,36.5 U8.B10@67,37
RAM_D34: U8.A10 U11.29 | length 41.1
  Top Layer w0.15: U11.29@58.675,18.575 58.675,19.83 ccw(c58.555,19.83) 58.555,19.95 58.495,19.95 cw(c58.495,20.07) 58.375,20.07 58.375,20.13 cw(c58.495,20.13) 58.495,20.25 58.855,20.25 ccw(c58.855,20.37) 58.975,20.37 58.975,20.43 ccw(c58.855,20.43) 58.855,20.55 58.495,20.55 cw(c58.495,20.67) 58.375,20.67 58.375,20.73 cw(c58.495,20.73) 58.495,20.85 58.555,20.85 ccw(c58.555,20.97) 58.675,20.97 58.675,21.275 58.908,21.508 cw(c58.993,21.423) 59.078,21.508 59.12,21.466 ; 59.121,21.466 ccw(c59.205,21.551) 59.29,21.466 59.333,21.508 ccw(c59.248,21.593) 59.333,21.678 ; 59.333,21.678 59.078,21.933 cw(c59.163,22.017) 59.078,22.102 59.12,22.145 cw(c59.205,22.06) 59.29,22.145 59.417,22.017 59.545,21.89 ; 59.545,21.89 ccw(c59.63,21.975) 59.714,21.89 59.757,21.933 ccw(c59.672,22.017) 59.757,22.102 ; 59.757,22.102 59.63,22.23 59.502,22.357 cw(c59.587,22.442) 59.502,22.526 59.545,22.569 cw(c59.63,22.484) 59.714,22.569 59.969,22.314 ccw(c60.054,22.399) 60.139,22.314 60.181,22.357 ccw(c60.096,22.442) 60.181,22.526 60.054,22.654 59.927,22.781 cw(c60.011,22.866) 59.927,22.951 59.969,22.993 cw(c60.054,22.908) 60.139,22.993 60.393,22.739 ccw(c60.478,22.824) 60.563,22.739 60.605,22.781 ccw(c60.521,22.866) 60.606,22.951 60.351,23.205 cw(c60.436,23.29) 60.351,23.375 60.393,23.418 cw(c60.478,23.333) 60.563,23.418 60.69,23.29 60.818,23.163 ccw(c60.902,23.248) 60.987,23.163 61.03,23.205 ccw(c60.945,23.29) 61.03,23.375 60.775,23.63 ; 60.775,23.63 cw(c60.86,23.715) 60.775,23.799 60.818,23.842 cw(c60.902,23.757) 60.987,23.842 ; 60.987,23.842 61.115,23.715 61.242,23.587 ccw(c61.327,23.672) 61.411,23.587 61.454,23.63 ccw(c61.369,23.715) 61.454,23.799 61.199,24.054 ; 61.199,24.054 cw(c61.284,24.139) 61.199,24.224 61.242,24.266 cw(c61.327,24.181) 61.411,24.266 ; 61.411,24.266 61.666,24.011 ccw(c61.751,24.096) 61.836,24.011 61.878,24.054 ccw(c61.793,24.139) 61.878,24.223 61.751,24.351 61.624,24.478 ; 61.623,24.478 cw(c61.708,24.563) 61.624,24.648 61.666,24.69 cw(c61.751,24.605) 61.836,24.69 ; 61.836,24.69 62.09,24.436 ccw(c62.175,24.521) 62.26,24.436 62.302,24.478 ccw(c62.218,24.563) 62.303,24.648 62.175,24.775 62.048,24.902 ; 62.048,24.903 cw(c62.133,24.987) 62.048,25.072 62.09,25.115 cw(c62.175,25.03) 62.26,25.115 ; 62.26,25.115 62.387,24.987 62.515,24.86 ccw(c62.599,24.945) 62.684,24.86 62.727,24.902 ccw(c62.642,24.987) 62.727,25.072 62.472,25.327 cw(c62.557,25.412) 62.472,25.496 62.515,25.539 cw(c62.599,25.454) 62.684,25.539 62.812,25.412 62.939,25.284 ccw(c63.024,25.369) 63.109,25.284 63.151,25.327 ccw(c63.066,25.412) 63.151,25.496 62.896,25.751 cw(c62.981,25.836) 62.896,25.921 62.939,25.963 cw(c63.024,25.878) 63.108,25.963 63.363,25.709 ccw(c63.448,25.793) 63.533,25.709 63.575,25.751 ccw(c63.49,25.836) 63.575,25.921 63.448,26.048 63.321,26.175 cw(c63.406,26.26) 63.321,26.345 63.363,26.387 cw(c63.448,26.303) 63.533,26.388 63.787,26.133 ; 63.788,26.133 ccw(c63.872,26.218) 63.957,26.133 64,26.175 ccw(c63.915,26.26) 64,26.345 ; 64,26.345 63.872,26.472 63.745,26.6 cw(c63.83,26.684) 63.745,26.769 63.787,26.812 cw(c63.872,26.727) 63.957,26.812 64.084,26.684 64.212,26.557 ccw(c64.296,26.642) 64.381,26.557 64.424,26.6 ccw(c64.339,26.684) 64.424,26.769 ; 64.424,26.769 64.169,27.024 cw(c64.254,27.109) 64.169,27.193 64.212,27.236 cw(c64.296,27.151) 64.381,27.236 64.509,27.109 64.636,26.981 ccw(c64.721,27.066) 64.806,26.981 64.848,27.024 ccw(c64.763,27.109) 64.848,27.193 64.593,27.448 cw(c64.678,27.533) 64.593,27.618 64.636,27.66 cw(c64.721,27.575) 64.806,27.66 64.933,27.533 65.06,27.406 ccw(c65.145,27.49) 65.23,27.406 65.272,27.448 ccw(c65.187,27.533) 65.272,27.618 65.145,27.745 65.018,27.872 cw(c65.103,27.957) 65.018,28.042 65.06,28.084 cw(c65.145,28) 65.23,28.085 65.484,27.83 ccw(c65.569,27.915) 65.654,27.83 65.697,27.872 ccw(c65.612,27.957) 65.697,28.042 ; 65.697,28.042 65.569,28.169 65.442,28.297 cw(c65.527,28.381) 65.442,28.466 65.484,28.509 cw(c65.569,28.424) 65.654,28.509 65.909,28.254 ; 65.909,28.254 ccw(c65.994,28.339) 66.078,28.254 66.121,28.297 ccw(c66.036,28.381) 66.121,28.466 ; 66.121,28.466 65.866,28.721 cw(c65.951,28.806) 65.866,28.89 65.909,28.933 cw(c65.994,28.848) 66.078,28.933 66.206,28.806 66.333,28.678 ccw(c66.418,28.763) 66.503,28.678 66.545,28.721 ccw(c66.46,28.806) 66.545,28.89 66.291,29.145 cw(c66.375,29.23) 66.291,29.315 66.333,29.357 cw(c66.418,29.272) 66.503,29.357 66.545,29.315 ccw(c66.63,29.4) 66.715,29.315 67,29.6 67,33.45 cw(c67,33.6) 67,33.75 ccw(c67,33.9) 67,34.05 cw(c67,34.2) 67,34.35 ccw(c67,34.5) 67,34.65 cw(c67,34.8) 67,34.95 ccw(c67,35.1) 67,35.25 U8.A10@67,36
RAM_D35: U8.C11 U11.30 | length 41.5
  Top Layer w0.15: U11.30@58.025,18.575 58.025,22.075 58.31,22.36 cw(c58.395,22.275) 58.48,22.36 58.522,22.318 ccw(c58.607,22.403) 58.692,22.318 58.734,22.36 ccw(c58.65,22.445) 58.735,22.53 58.48,22.784 cw(c58.565,22.869) 58.48,22.954 58.522,22.997 cw(c58.607,22.912) 58.692,22.997 58.819,22.869 58.947,22.742 ccw(c59.031,22.827) 59.116,22.742 59.159,22.784 ccw(c59.074,22.869) 59.159,22.954 58.904,23.209 cw(c58.989,23.294) 58.904,23.378 58.947,23.421 cw(c59.031,23.336) 59.116,23.421 59.371,23.166 ccw(c59.456,23.251) 59.541,23.166 59.583,23.209 ccw(c59.498,23.294) 59.583,23.378 59.456,23.506 59.328,23.633 cw(c59.413,23.718) 59.328,23.803 59.371,23.845 cw(c59.456,23.76) 59.54,23.845 59.795,23.591 ccw(c59.88,23.675) 59.965,23.591 60.007,23.633 ccw(c59.922,23.718) 60.007,23.803 ; 59.965,24.27 ccw(c59.88,24.185) 59.795,24.269 59.753,24.227 ccw(c59.838,24.142) 59.753,24.057 59.88,23.93 60.007,23.803 ; 59.965,24.269 60.092,24.142 60.219,24.015 ccw(c60.304,24.1) 60.389,24.015 ; 60.177,24.482 cw(c60.262,24.566) 60.177,24.651 60.219,24.694 cw(c60.304,24.609) 60.389,24.694 ; 60.177,24.482 60.432,24.227 ; 60.389,24.015 60.432,24.057 ccw(c60.347,24.142) 60.432,24.227 ; 60.389,24.694 60.516,24.566 60.644,24.439 ; 60.601,24.906 cw(c60.686,24.991) 60.601,25.075 60.644,25.118 cw(c60.729,25.033) 60.813,25.118 60.941,24.991 61.068,24.863 ccw(c61.153,24.948) 61.238,24.863 61.28,24.906 ccw(c61.195,24.991) 61.28,25.075 61.153,25.203 61.025,25.33 cw(c61.11,25.415) 61.025,25.5 61.068,25.542 cw(c61.153,25.457) 61.237,25.542 61.492,25.288 ccw(c61.577,25.372) 61.662,25.288 61.704,25.33 ccw(c61.619,25.415) 61.704,25.5 61.577,25.627 61.45,25.754 cw(c61.535,25.839) 61.45,25.924 61.492,25.966 cw(c61.577,25.882) 61.662,25.966 61.916,25.712 ccw(c62.001,25.797) 62.086,25.712 62.129,25.754 ccw(c62.044,25.839) 62.129,25.924 61.874,26.179 cw(c61.959,26.263) 61.874,26.348 61.916,26.391 cw(c62.001,26.306) 62.086,26.391 62.213,26.263 62.341,26.136 ccw(c62.426,26.221) 62.51,26.136 62.553,26.179 ccw(c62.468,26.263) 62.553,26.348 62.298,26.603 cw(c62.383,26.688) 62.298,26.773 62.341,26.815 cw(c62.426,26.73) 62.51,26.815 62.638,26.688 62.765,26.56 ccw(c62.85,26.645) 62.935,26.56 62.977,26.603 ccw(c62.892,26.688) 62.977,26.772 62.85,26.9 62.723,27.027 ; 60.601,24.906 60.856,24.651 cw(c60.771,24.566) 60.856,24.482 60.813,24.439 cw(c60.729,24.524) 60.644,24.439 ; 62.722,27.027 cw(c62.807,27.112) 62.723,27.197 62.765,27.239 cw(c62.85,27.154) 62.935,27.239 ; 62.935,27.239 63.189,26.985 ; 63.147,27.451 63.274,27.324 63.401,27.197 ; 63.147,27.452 cw(c63.232,27.536) 63.147,27.621 63.189,27.664 ; 63.189,26.985 ccw(c63.274,27.07) 63.359,26.985 63.401,27.027 ccw(c63.317,27.112) 63.402,27.197 ; 63.189,27.664 cw(c63.274,27.579) 63.359,27.664 63.614,27.409 ; 63.614,27.409 ccw(c63.698,27.494) 63.783,27.409 63.826,27.451 ccw(c63.741,27.536) 63.826,27.621 63.571,27.876 cw(c63.656,27.96) 63.571,28.045 63.613,28.088 cw(c63.698,28.003) 63.783,28.088 63.91,27.96 64.038,27.833 ccw(c64.123,27.918) 64.207,27.833 64.25,27.876 ccw(c64.165,27.96) 64.25,28.045 63.995,28.3 cw(c64.08,28.385) 63.995,28.47 64.038,28.512 cw(c64.123,28.427) 64.207,28.512 64.335,28.385 64.462,28.257 ccw(c64.547,28.342) 64.632,28.257 64.674,28.3 ccw(c64.589,28.385) 64.674,28.47 64.42,28.724 cw(c64.504,28.809) 64.42,28.894 64.462,28.936 cw(c64.547,28.851) 64.632,28.936 64.886,28.682 ccw(c64.971,28.767) 65.056,28.682 65.098,28.724 ccw(c65.014,28.809) 65.099,28.894 64.971,29.021 64.844,29.148 cw(c64.929,29.233) 64.844,29.318 64.886,29.361 cw(c64.971,29.276) 65.056,29.361 65.311,29.106 ccw(c65.395,29.191) 65.48,29.106 65.523,29.148 ccw(c65.438,29.233) 65.523,29.318 65.395,29.445 65.268,29.573 cw(c65.353,29.658) 65.268,29.742 65.311,29.785 cw(c65.395,29.7) 65.48,29.785 65.608,29.658 65.735,29.53 ccw(c65.82,29.615) 65.905,29.53 65.947,29.573 ccw(c65.862,29.658) 65.947,29.742 65.692,29.997 cw(c65.777,30.082) 65.692,30.167 65.735,30.209 cw(c65.82,30.124) 65.904,30.209 66.032,30.082 66.159,29.955 ccw(c66.244,30.039) 66.329,29.955 66.371,29.997 ccw(c66.286,30.082) 66.371,30.167 66.329,30.209 cw(c66.414,30.294) 66.329,30.379 ; U8.C11@66.025,38.025 66.025,37.975 66.5,37.5 66.5,30.55 66.329,30.379
RAM_LDN: U8.B1 U11.85 | length 43.5
  Top Layer w0.15: U8.B1@76,37 76.7,37 v2(77.06,36.64) ; v2@76.885,36.64 ccw(c76.463,36.64) 76.762,36.938 ccw(c77.06,37.237) v2@77.06,36.815 ; U11.85@78.075,7.375 79.375,7.375 81.45,9.45 81.45,32.25 v2(81.15,32.55) ; v2@81.15,32.375 cw(c81.15,31.953) 81.449,32.251 cw(c81.747,32.55) v2@81.325,32.55
  Bottom Layer w0.15: v2(77.06,36.64) 77.35,36.35 ; v2@77.064,36.465 cw(c77.073,36.073) 77.35,36.35 ; v2@77.235,36.636 ccw(c77.627,36.627) 77.35,36.35 ; v2@80.975,32.55 ccw(c80.553,32.55) 80.851,32.849 ccw(c81.15,33.147) v2@81.15,32.725 ; v2(81.15,32.55) 80.55,33.15 cw(c80.656,33.256) 80.55,33.363 80.567,33.38 ccw(c80.444,33.504) 80.567,33.628 ccw(c80.444,33.504) 80.32,33.628 80.072,33.38 cw(c79.949,33.504) 79.825,33.38 cw(c79.949,33.504) 79.825,33.628 80.072,33.875 ccw(c79.949,33.999) 80.072,34.123 ccw(c79.949,33.999) 79.825,34.123 79.701,33.999 79.577,33.875 cw(c79.454,33.999) 79.33,33.875 cw(c79.454,33.999) 79.33,34.123 79.577,34.37 ccw(c79.454,34.494) 79.577,34.618 ccw(c79.454,34.494) 79.33,34.618 79.082,34.37 cw(c78.959,34.494) 78.835,34.37 cw(c78.959,34.494) 78.835,34.618 79.082,34.865 ccw(c78.959,34.989) 79.082,35.113 ccw(c78.959,34.989) 78.835,35.113 78.587,34.865 cw(c78.464,34.989) 78.34,34.865 cw(c78.464,34.989) 78.34,35.113 78.587,35.36 ccw(c78.464,35.484) 78.587,35.608 ccw(c78.464,35.484) 78.34,35.608 78.092,35.36 cw(c77.969,35.484) 77.845,35.36 cw(c77.969,35.484) 77.845,35.608 78.092,35.855 ccw(c77.969,35.979) 78.092,36.103 ccw(c77.969,35.979) 77.845,36.103 77.597,35.855 cw(c77.474,35.979) 77.35,35.855 cw(c77.474,35.979) 77.35,36.103 ccw(c77.226,36.226) 77.35,36.35
RAM_OEN: U8.B2 U11.86 | length 41.1
  Top Layer w0.15: U8.B2@75,37 75.104,37 75.604,36.5 76.4,36.5 77.145,35.755 ccw(c77.269,35.879) 77.392,35.755 cw(c77.516,35.631) 77.64,35.755 cw(c77.516,35.631) 77.64,35.508 77.392,35.26 ccw(c77.516,35.136) 77.392,35.013 ccw(c77.516,35.136) 77.64,35.013 77.887,35.26 cw(c78.011,35.136) 78.135,35.26 cw(c78.011,35.136) 78.135,35.013 77.887,34.765 ccw(c78.011,34.641) 77.887,34.518 ccw(c78.011,34.641) 78.135,34.518 78.382,34.765 cw(c78.506,34.641) 78.63,34.765 cw(c78.506,34.641) 78.63,34.518 78.382,34.27 ccw(c78.506,34.146) 78.382,34.023 ccw(c78.506,34.146) 78.63,34.023 78.877,34.27 cw(c79.001,34.146) 79.125,34.27 cw(c79.001,34.146) 79.125,34.023 79.001,33.899 78.877,33.775 ccw(c79.001,33.651) 78.877,33.528 ccw(c79.001,33.651) 79.125,33.528 79.372,33.775 cw(c79.496,33.651) 79.62,33.775 cw(c79.496,33.651) 79.62,33.528 79.372,33.28 ccw(c79.496,33.156) 79.372,33.033 ccw(c79.496,33.156) 79.62,33.033 79.867,33.28 cw(c79.991,33.156) 80.115,33.28 cw(c79.991,33.156) 80.115,33.033 79.867,32.785 ccw(c79.991,32.661) 79.867,32.538 ccw(c79.991,32.661) 80.115,32.538 80.362,32.785 cw(c80.486,32.661) 80.61,32.785 cw(c80.486,32.661) 80.61,32.538 80.575,32.503 ccw(c80.664,32.414) 80.575,32.325 81.2,31.7 81.2,9.85 79.375,8.025 U11.86@78.075,8.025
RAM_WEN: U8.A2 U11.88 | length 41.3
  Top Layer w0.15: U8.A2@75,36 75,35.05 76.232,33.818 ccw(c76.338,33.924) 76.444,33.818 76.514,33.889 cw(c76.62,33.783) 76.727,33.889 cw(c76.62,33.783) 76.727,33.677 76.656,33.606 ccw(c76.762,33.5) 76.656,33.394 ccw(c76.762,33.5) 76.868,33.394 76.939,33.465 cw(c77.045,33.359) 77.151,33.465 cw(c77.045,33.359) 77.151,33.253 76.974,33.076 76.797,32.899 ccw(c76.903,32.793) 76.797,32.687 ccw(c76.903,32.793) 77.009,32.687 77.186,32.864 77.363,33.041 cw(c77.469,32.934) 77.575,33.04 cw(c77.469,32.934) 77.575,32.828 77.398,32.652 77.222,32.475 ccw(c77.328,32.369) 77.222,32.263 ccw(c77.328,32.369) 77.434,32.263 77.61,32.44 77.787,32.616 cw(c77.893,32.51) 77.999,32.616 cw(c77.893,32.51) 77.999,32.404 77.646,32.051 ccw(c77.752,31.945) 77.646,31.839 ccw(c77.752,31.945) 77.858,31.839 78.035,32.015 78.211,32.192 cw(c78.318,32.086) 78.424,32.192 cw(c78.318,32.086) 78.424,31.98 78.247,31.803 78.07,31.626 ccw(c78.176,31.52) 78.07,31.414 ccw(c78.176,31.52) 78.282,31.414 78.459,31.591 78.636,31.768 cw(c78.742,31.662) 78.848,31.768 cw(c78.742,31.662) 78.848,31.556 78.671,31.379 78.494,31.202 ccw(c78.6,31.096) 78.494,30.99 ccw(c78.6,31.096) 78.707,30.99 79.06,31.343 cw(c79.166,31.237) 79.272,31.343 cw(c79.166,31.237) 79.272,31.131 79.095,30.955 78.92,30.779 ccw(c79.026,30.673) 78.92,30.567 ccw(c79.026,30.673) 79.132,30.567 79.308,30.742 79.484,30.919 cw(c79.59,30.813) 79.696,30.919 cw(c79.59,30.813) 79.696,30.707 79.344,30.355 ccw(c79.45,30.249) 79.344,30.143 ccw(c79.45,30.249) 79.556,30.143 79.732,30.318 79.909,30.495 cw(c80.015,30.389) 80.121,30.495 cw(c80.015,30.389) 80.121,30.283 80.05,30.212 ccw(c80.156,30.106) 80.05,30 80.375,29.675 80.7,29.351 80.7,10.75 79.275,9.325 U11.88@78.075,9.325
RAM_ZZ: U8.F16 U11.64 | length 45
  Top Layer w0.15: v1@60.55,41.3 cw(c60.55,40.938) 60.806,41.194 cw(c61.062,41.45) v1@60.7,41.45 ; v1(60.55,41.45) U8.F16@61,41 ; U11.64@66.475,3.325 66.475,15.175 v1(67.15,15.85) ; v1@67,15.85 cw(c66.638,15.85) 66.894,15.594 cw(c67.15,15.338) v1@67.15,15.7
  Mid-Layer 2 w0.15: v1@60.55,41.3 cw(c60.55,40.817) 60.891,41.159 ; v1(60.55,41.45) 60.55,41.5 60.95,41.1 60.95,40.384 59.925,39.359 59.925,23.075 v1(67.15,15.85) ; v1@60.7,41.45 ccw(c60.941,41.45) 60.771,41.279 ; v1@67,15.85 ccw(c66.638,15.85) 66.894,16.106 ccw(c67.15,16.362) v1@67.15,16
RX1: C111-1.1 C112-1.2 U21.3 | length 21.9
  Top Layer w0.15: v2(125.35,44.55) 125.375,44.525 U21.3@126.4,44.525 ; v2@125.474,44.426 cw(c125.712,44.188) 125.712,44.525 ; v2@125.474,44.674 ccw(c125.833,45.033) U21.3@125.833,44.525 ; v2@133.526,34.376 cw(c133.201,34.051) 133.661,34.051 ; v2@133.526,34.624 ccw(c133.201,34.949) 133.661,34.949 ; v2(133.65,34.5) v2@133.661,34.511 ; C111-1.1@133.661,31.358 v2@133.661,34.511 ; 133.661,34.104 cw(c134.046,34.104) v2@133.774,34.376 ; 133.661,34.896 ccw(c134.046,34.896) v2@133.774,34.624 ; C112-1.2@133.661,35.358 v2@133.661,34.511
  MidLayer1 w0.15: v2@125.35,44.375 cw(c125.35,43.953) 125.649,44.251 cw(c125.947,44.55) v2@125.525,44.55 ; v2(125.35,44.55) 133.65,36.25 v2(133.65,34.5) ; v2@133.526,34.624 ccw(c133.228,34.922) 133.65,34.922 ccw(c134.072,34.922) v2@133.774,34.624
RX1_CLK/2: U8.G3 U12-1.40 | length 65.1
  Top Layer w0.15: U8.G3@74,42 74.5,41.5 75.15,41.5 75.5,41.85 75.5,42.3 75.7,42.5 79.455,42.5 cw(c79.455,42.28) 79.675,42.28 79.675,42.181 ccw(c79.895,42.181) 79.895,41.961 80.005,41.961 ccw(c80.005,42.181) 80.225,42.181 80.225,42.28 cw(c80.445,42.28) 80.445,42.5 80.7,42.5 85.65,37.55 v1(86.5,37.55) ; v1@86.394,37.444 ccw(c86.138,37.188) 86.138,37.55 ccw(c86.138,37.912) v1@86.394,37.656
  Top Layer w0.2: U12-1.40@122.957,15.961 ccw(c123.614,15.961) v1@123.149,15.497 ; U12-1.40@122.957,16.063 122.957,15.512 v1(123.061,15.408)
  MidLayer1 w0.15: v1@86.5,37.4 cw(c86.5,37.038) 86.756,37.294 cw(c87.012,37.55) v1@86.65,37.55 ; v1(86.5,37.55) 109.043,15.007 117.813,15.007 117.814,15.008 122.661,15.008 v1(123.061,15.408) ; v1@122.911,15.408 cw(c122.549,15.408) 122.805,15.152 cw(c123.061,14.896) v1@123.061,15.258
RX1CLK: R158-1.2 R159-1.1 U5.18 U12-1.17 | length 64
  Top Layer w0.15: U5.18@84.25,64.175 84.25,63.65 v2(85.35,62.55) ; v2@85.175,62.55 ccw(c84.753,62.55) 85.051,62.849 ccw(c85.35,63.147) v2@85.35,62.725 ; v1(115.261,19.858) R158-1.2@116.111,19.858 116.141,19.888 U12-1.17@119.632,19.888 ; v1@115.367,19.752 cw(c115.623,19.496) 115.623,19.858 cw(c115.623,20.22) v1@115.367,19.964
  Mid-Layer 2 w0.15: v2@85.35,62.375 cw(c85.35,61.953) 85.649,62.251 cw(c85.947,62.55) v2@85.525,62.55 ; v2(85.35,62.55) 85.8,62.1 91.5,56.4 91.5,47.05 94.05,44.5 94.05,41.069 v1(115.261,19.858) ; v1@115.111,19.858 ccw(c114.749,19.858) 115.005,20.114 ccw(c115.261,20.37) v1@115.261,20.008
